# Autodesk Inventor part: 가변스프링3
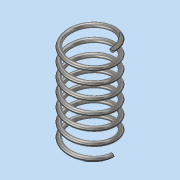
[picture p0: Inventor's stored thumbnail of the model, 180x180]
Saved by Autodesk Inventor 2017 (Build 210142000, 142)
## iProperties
Part Number: 가변스프링3
Material: 스테인레스 스틸
Document SubType Name: Modeling
Designer: MRC
Density: 8 g/cm^3
Appearance: 반연마
Mass: 10.9602 g
Surface Area: 27.6886 cm^2
Volume: 1.37003 cm^3
Author: MRC
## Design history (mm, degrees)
sketch "스케치1"
  geometry: L1 (0, 0)-(10, 0); L2 (10, 0)-(10, 41.641); L3 (10, 41.641)-(0, 41.641); L4 (0, 41.641)-(0, 0); C1 r 1 at (10, 0)
  constraints: 8 end point, 2 parallel, 1 centre point, 1 coincident, 1 horizontal, 1 perpendicular
  dimensions: "d0" = 20 diameter of L2 L4; "d1" = 41.64078 distance of L1.end L2.end (derived); "d2" = 2 diameter of C1
feature "코일1" sketch "스케치1" pitch "d3" = 10; turns "d5" = 7; dims "d4" = 41.64078 (= d1), "d6" = 0, angle "d7" = 90 deg, angle "d8" = 90 deg, "d9" = 0, "d10" = 0
sketch "스케치2"
  geometry: L1 (-15, 41.641)-(15, 41.641); L2 (15, 41.641)-(15, 0); L3 (15, 0)-(-15, 0); L4 (-15, 0)-(-15, 41.641); L5 (0, 41.641)-(0, 0) reference; 2 further points
  constraints: 8 end point, 2 midpoint, 2 parallel, 1 coincident, 1 horizontal, 1 perpendicular
  dimensions: "d11" = 30 distance of L1.start L1.end
extrude "돌출1" sketch "스케치2" stored distance "d12" = 0; taper "d13" = 0 deg
node "솔리드1"
